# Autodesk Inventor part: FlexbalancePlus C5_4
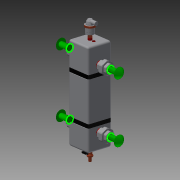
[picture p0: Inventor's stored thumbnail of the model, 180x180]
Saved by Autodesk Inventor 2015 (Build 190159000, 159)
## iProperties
allow_slope_adjustment: 0 ul
connection_type: 13 ul
flow_configuration2: 1 ul
flow_direction: 2 ul
loss_method: 0 ul
radius: 19,750 mm
description: 0:0:28378_Flexbalance Ecoplus C5_4
manufacturer: 0:0:Flamco Group
model: 0:0:Flexbalance
url: 0:0:http://www.flamcogroup.com
connection_type: 10 ul
Created: 2015-10
Part Number: FlexbalancePlus C5_4
Material: Generic
Document SubType Name: Modeling
Designer: edwin
Density: 1 g/cm^3
Appearance: Default
Mass: 9791.15 g
Surface Area: 4222.26 cm^2
Volume: 9791.15 cm^3
Author: edwin
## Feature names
1. Revolution1
2. Revolution2
3. Extrusion1
4. Fillet2
5. Extrusion21
6. Circular Pattern8
7. Revolution3
8. Sweep1
9. Extrusion3
10. Extrusion4
11. Extrusion5
12. Rectangular Pattern1
13. Revolution4
14. Extrusion6
15. Circular Pattern1
16. Extrusion23
17. Circular Pattern10
18. Extrusion8
19. Circular Pattern3
20. Extrusion12
21. Rectangular Pattern4
22. Revolution5
23. Extrusion13
24. Extrusion9
25. Circular Pattern4
26. Extrusion22
27. Circular Pattern9
28. Extrusion11
29. Circular Pattern6
30. Rectangular Pattern5
31. Revolution6
32. Extrusion15
33. Circular Pattern7
34. Extrusion16
35. Fillet3
36. Extrusion17
37. Extrusion18
38. Extrusion19
39. Extrusion20
40. Fillet4
## Parameters: d0 = 90 deg, d1 = 90 deg, d2 = 42 mm, d4 = 14.4 mm, d5 = 0, d8 = 1.5 mm, d9 = 90 deg, d10 = 15 mm, d13 = 252.5 mm, d14 = 0, d15 = 0, d17 = 0, d19 = 0, d20 = 2.5 mm, d22 = 0, d25 = -233 mm, d26 = 90 deg, d29 = 0, d31 = 360 deg, d39 = 22 mm, d40 = 0, d42 = 360 deg, d47 = 90 deg, d49 = 22 mm, d50 = 0, d52 = 360 deg, d60 = 22 mm, d61 = 0, d63 = 360 deg, d68 = 39.5 mm, d70 = 0, d74 = 39.5 mm, d76 = 0, d79 = 321 mm, d80 = 90 deg, d85 = 6 mm, d86 = 0, d88 = 360 deg, d90 = 15.5 mm, d91 = 6 mm, d92 = 0, d93 = 1 mm, d94 = 16.6 mm, d95 = 3.5 mm, d96 = 0, d97 = 9 mm, d98 = 0, d99 = 3 mm, d100 = 0, d101 = 11.5 mm, d103 = 0, d104 = 1.5 mm, d106 = 14 mm, d107 = 0, d109 = 360 deg, d112 = 20.8 mm, d113 = 0, d115 = 360 deg, d117 = 20.8 mm, d118 = 0, d120 = 360 deg
